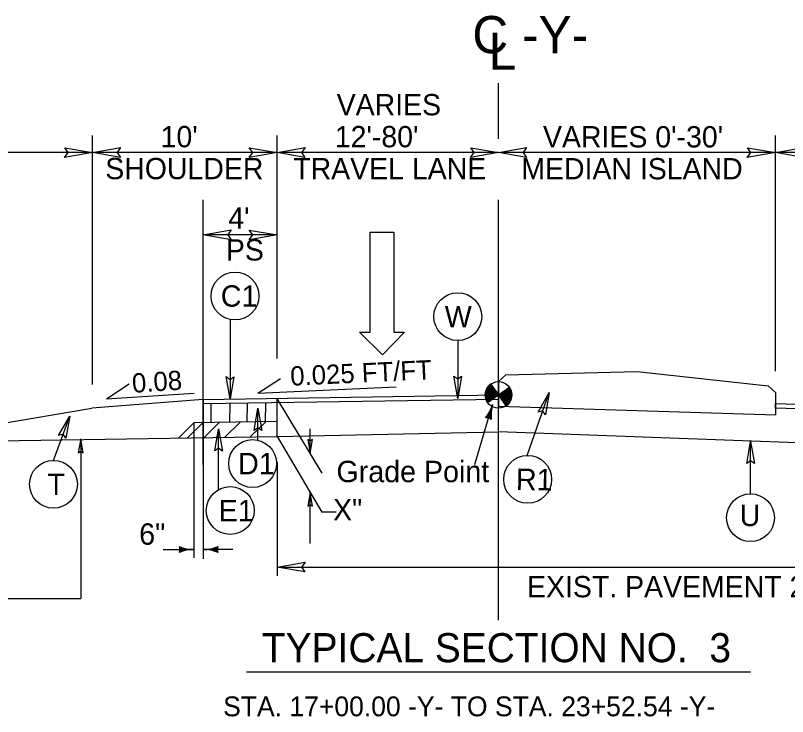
# Model space of a CAD drawing. Extents: x 2176156 to 2177167, y 76401 to 76644.
# Drawn here: x 2176967.78 to 2177009.62, y 76584.23 to 76622.21 of the extents above; entities that cross this region are included whole.
import ezdxf

# ---------------------------------------------------------------- set-up
doc = ezdxf.new("R2010")
doc.units = 0
for name, color, linetype in [('Exist Building', 7, 'Continuous'), ('Exist Building Metal Canopy', 7, 'Continuous'), ('Exist Roads Change in Surface', 7, 'Continuous'), ('Exist Roads Curbs', 7, 'Continuous'), ('Exist Roads EOP Other', 7, 'Continuous'), ('Exist Roads Soil', 7, 'Continuous'), ('Exist Structure Minor Culvert Topo', 7, 'Continuous'), ('Exist Structure Minor Drop Inlet', 7, 'Continuous'), ('Exist Utilities Other Pole CELL', 7, 'Continuous'), ('Exist Vegetation Woods Line', 7, 'Continuous'), ('Model Boundary Lines Text', 7, 'Continuous'), ('Old_Level_1', 7, 'Continuous'), ('Old_Level_3', 7, 'Continuous'), ('Prop North Arrow NAD83 for Plan Sheets CELL', 7, 'Continuous'), ('Sheet Plan CELL', 7, 'Continuous')]:
    doc.layers.add(name, color=color, linetype=linetype)

msp = doc.modelspace()

# ---------------------------------------------------------------- linework, layer by layer
at = {"layer": 'Exist Building'}
for p, q in [((2176981.96, 76599.4), (2176981.96, 76601.472)), ((2176960.844, 76599.085), (2176981.96, 76599.4))]:
    msp.add_line(p, q, dxfattribs=at)
at = {"layer": 'Exist Roads Change in Surface'}
for p, q in [((2176993.548, 76602.242), (2176993.96, 76601.65)), ((2176993.96, 76601.65), (2176994.551, 76602.062)), ((2176993.367, 76601.24), (2176993.96, 76601.65)), ((2176993.96, 76601.65), (2176993.367, 76601.24)), ((2176994.371, 76601.059), (2176993.96, 76601.65))]:
    msp.add_line(p, q, dxfattribs=at)
for points in [[(2176993.714, 76602.003), (2176993.239, 76601.672)], [(2176993.723, 76601.991), (2176993.239, 76601.654)], [(2176993.731, 76601.979), (2176993.239, 76601.637)], [(2176993.698, 76602.026), (2176993.24, 76601.708)], [(2176993.706, 76602.015), (2176993.24, 76601.69)], [(2176993.739, 76601.967), (2176993.24, 76601.62)], [(2176993.747, 76601.956), (2176993.24, 76601.602)], [(2176993.756, 76601.944), (2176993.242, 76601.586)], [(2176993.69, 76602.038), (2176993.243, 76601.727)], [(2176993.764, 76601.932), (2176993.243, 76601.57)], [(2176993.682, 76602.05), (2176993.245, 76601.746)], [(2176993.673, 76602.062), (2176993.247, 76601.766)], [(2176993.665, 76602.074), (2176993.251, 76601.786)], [(2176993.657, 76602.086), (2176993.256, 76601.807)], [(2176993.649, 76602.098), (2176993.261, 76601.828)], [(2176993.64, 76602.109), (2176993.267, 76601.85)], [(2176993.632, 76602.121), (2176993.273, 76601.871)], [(2176993.624, 76602.133), (2176993.281, 76601.894)], [(2176993.616, 76602.145), (2176993.29, 76601.918)], [(2176993.607, 76602.157), (2176993.3, 76601.943)], [(2176993.599, 76602.168), (2176993.313, 76601.969)], [(2176993.591, 76602.18), (2176993.327, 76601.996)], [(2176993.583, 76602.192), (2176993.343, 76602.026)], [(2176993.574, 76602.204), (2176993.363, 76602.057)], [(2176993.566, 76602.216), (2176993.39, 76602.093)], [(2176993.558, 76602.228), (2176993.424, 76602.134)], [(2176993.55, 76602.239), (2176993.485, 76602.195)], [(2176994.555, 76602.057), (2176994.555, 76602.057), (2176993.963, 76601.645)], [(2176994.563, 76602.045), (2176993.972, 76601.633)], [(2176994.57, 76602.032), (2176993.98, 76601.622)], [(2176994.578, 76602.021), (2176993.988, 76601.61)], [(2176994.585, 76602.008), (2176993.996, 76601.598)], [(2176994.592, 76601.995), (2176994.004, 76601.586)], [(2176994.599, 76601.982), (2176994.013, 76601.574)], [(2176994.606, 76601.97), (2176994.021, 76601.562)], [(2176994.613, 76601.957), (2176994.029, 76601.551)], [(2176994.619, 76601.943), (2176994.037, 76601.539)], [(2176994.624, 76601.929), (2176994.046, 76601.527)], [(2176993.772, 76601.92), (2176993.245, 76601.553)], [(2176993.78, 76601.908), (2176993.248, 76601.538)], [(2176993.789, 76601.896), (2176993.251, 76601.522)], [(2176993.797, 76601.884), (2176993.254, 76601.507)], [(2176993.805, 76601.873), (2176993.257, 76601.491)], [(2176993.813, 76601.861), (2176993.26, 76601.476)], [(2176993.821, 76601.849), (2176993.264, 76601.461)], [(2176993.83, 76601.837), (2176993.268, 76601.447)], [(2176993.838, 76601.825), (2176993.273, 76601.432)], [(2176993.846, 76601.813), (2176993.278, 76601.418)], [(2176993.854, 76601.802), (2176993.283, 76601.404)], [(2176993.863, 76601.79), (2176993.288, 76601.39)], [(2176993.871, 76601.778), (2176993.294, 76601.376)], [(2176993.879, 76601.766), (2176993.299, 76601.363)], [(2176993.887, 76601.754), (2176993.305, 76601.349)], [(2176993.896, 76601.743), (2176993.312, 76601.336)], [(2176993.904, 76601.731), (2176993.317, 76601.323)], [(2176993.912, 76601.719), (2176993.324, 76601.31)], [(2176993.92, 76601.707), (2176993.331, 76601.297)], [(2176993.929, 76601.695), (2176993.338, 76601.284)], [(2176993.937, 76601.683), (2176993.346, 76601.272)], [(2176993.945, 76601.671), (2176993.353, 76601.26)], [(2176993.953, 76601.66), (2176993.362, 76601.248), (2176993.362, 76601.248)], [(2176994.63, 76601.916), (2176994.054, 76601.515)], [(2176994.635, 76601.902), (2176994.062, 76601.503)], [(2176994.64, 76601.888), (2176994.07, 76601.491)], [(2176994.645, 76601.874), (2176994.079, 76601.48)], [(2176994.65, 76601.859), (2176994.087, 76601.468)], [(2176994.654, 76601.845), (2176994.095, 76601.456)], [(2176994.658, 76601.83), (2176994.103, 76601.444)], [(2176994.661, 76601.815), (2176994.112, 76601.432)], [(2176994.664, 76601.799), (2176994.12, 76601.42)], [(2176994.667, 76601.784), (2176994.128, 76601.409)], [(2176994.67, 76601.768), (2176994.136, 76601.397)], [(2176994.673, 76601.753), (2176994.145, 76601.385)], [(2176994.675, 76601.736), (2176994.153, 76601.373)], [(2176994.676, 76601.72), (2176994.161, 76601.361)], [(2176994.678, 76601.703), (2176994.169, 76601.349)], [(2176994.68, 76601.687), (2176994.177, 76601.338)], [(2176994.68, 76601.67), (2176994.186, 76601.326)], [(2176994.68, 76601.652), (2176994.194, 76601.314)], [(2176994.679, 76601.634), (2176994.202, 76601.302)], [(2176994.68, 76601.617), (2176994.21, 76601.29)], [(2176994.679, 76601.599), (2176994.219, 76601.278)], [(2176994.677, 76601.579), (2176994.227, 76601.266)], [(2176994.674, 76601.56), (2176994.235, 76601.255)], [(2176994.672, 76601.541), (2176994.243, 76601.243)], [(2176994.668, 76601.521), (2176994.252, 76601.231)], [(2176994.665, 76601.501), (2176994.26, 76601.219)], [(2176994.66, 76601.48), (2176994.268, 76601.207)], [(2176994.654, 76601.458), (2176994.276, 76601.196)], [(2176994.647, 76601.436), (2176994.285, 76601.184)], [(2176994.64, 76601.413), (2176994.293, 76601.172)], [(2176994.631, 76601.39), (2176994.301, 76601.16)], [(2176994.621, 76601.365), (2176994.309, 76601.148)], [(2176994.609, 76601.34), (2176994.317, 76601.136)], [(2176994.597, 76601.313), (2176994.326, 76601.125)], [(2176994.58, 76601.284), (2176994.334, 76601.113)], [(2176994.56, 76601.253), (2176994.342, 76601.101)], [(2176994.536, 76601.218), (2176994.35, 76601.089)], [(2176994.503, 76601.178), (2176994.359, 76601.077)], [(2176994.451, 76601.124), (2176994.367, 76601.065)]]:
    msp.add_lwpolyline(points, dxfattribs=at)
msp.add_circle((2176993.959, 76601.651), 0.721, dxfattribs=at)
for start, end in [(124.8249, 214.8249), (304.8249, 34.8249)]:
    msp.add_arc((2176993.959, 76601.651), 0.721, start, end, dxfattribs=at)
at = {"layer": 'Exist Roads Curbs'}
for points in [[(2176977.96, 76601.413), (2176993.96, 76601.65), (2176993.96, 76601.65), (2176993.96, 76601.4), (2176993.96, 76601.4), (2176977.96, 76601.163)], [(2177008.961, 76601.183), (2177008.96, 76601.183), (2177024.96, 76600.684), (2177024.96, 76600.433), (2177008.96, 76600.933), (2177008.96, 76600.933)]]:
    msp.add_lwpolyline(points, close=True, dxfattribs=at)
at = {"layer": 'Exist Roads EOP Other'}
msp.add_line((2176977.947, 76601.413), (2176971.912, 76600.93), dxfattribs=at)
at = {"layer": 'Exist Roads Soil'}
for p, q in [((2176994.354, 76602.743), (2177001.464, 76602.928)), ((2177001.464, 76602.928), (2177008.566, 76602.153)), ((2176993.96, 76602.379), (2176994.354, 76602.743)), ((2176993.96, 76602.379), (2176993.96, 76601.044)), ((2177008.961, 76601.79), (2177008.566, 76602.153)), ((2177008.961, 76601.79), (2177008.961, 76600.576)), ((2176977.96, 76601.413), (2176977.958, 76600.146)), ((2176943.96, 76596.271), (2176971.912, 76600.93)), ((2176993.96, 76601.044), (2177008.961, 76600.576)), ((2176977.454, 76600.139), (2176976.631, 76599.32)), ((2176981.96, 76600.206), (2176977.454, 76600.139))]:
    msp.add_line(p, q, dxfattribs=at)
at = {"layer": 'Exist Structure Minor Drop Inlet'}
for p, q in [((2176987.006, 76605.044), (2176987.006, 76610.476)), ((2176987.006, 76610.476), (2176988.287, 76610.476)), ((2176988.287, 76610.476), (2176988.287, 76605.044)), ((2176987.666, 76603.822), (2176986.424, 76605.044)), ((2176986.424, 76605.044), (2176987.006, 76605.044)), ((2176988.869, 76605.044), (2176987.666, 76603.822)), ((2176988.287, 76605.044), (2176988.869, 76605.044))]:
    msp.add_line(p, q, dxfattribs=at)
at = {"layer": 'Exist Utilities Other Pole CELL'}
for p, q in [((2176980.91, 76601.743), (2176982.15, 76602.539)), ((2176972.719, 76601.434), (2176973.944, 76602.253)), ((2176980.91, 76601.743), (2176988.409, 76602.093)), ((2176972.719, 76601.434), (2176977.465, 76601.747))]:
    msp.add_line(p, q, dxfattribs=at)
at = {"layer": 'Model Boundary Lines Text'}
for p, q in [((2176978.377, 76600.154), (2176978.392, 76601.171)), ((2176979.395, 76600.168), (2176979.41, 76601.182)), ((2176980.336, 76600.175), (2176980.35, 76601.201)), ((2176981.333, 76600.199), (2176981.348, 76601.211)), ((2176977.103, 76599.333), (2176977.93, 76600.143)), ((2176977.997, 76599.351), (2176978.832, 76600.17)), ((2176979.116, 76599.355), (2176979.951, 76600.174)), ((2176980.524, 76599.396), (2176981.359, 76600.215)), ((2176980.299, 76586.643), (2177007.62, 76586.643))]:
    msp.add_line(p, q, dxfattribs=at)
at = {"layer": 'Old_Level_1'}
for points in [[(2176970.45, 76615.041), (2176971.96, 76614.781), (2176970.442, 76614.513), (2176970.635, 76614.781)], [(2176973.469, 76614.521), (2176971.96, 76614.781), (2176973.478, 76615.049), (2176973.285, 76614.781)], [(2176980.45, 76615.041), (2176981.96, 76614.781), (2176980.442, 76614.513), (2176980.635, 76614.781)], [(2176983.469, 76614.521), (2176981.96, 76614.781), (2176983.478, 76615.049), (2176983.285, 76614.781)], [(2176992.45, 76615.041), (2176993.96, 76614.781), (2176992.442, 76614.513), (2176992.635, 76614.781)], [(2176995.469, 76614.521), (2176993.96, 76614.781), (2176995.478, 76615.049), (2176995.285, 76614.781)], [(2177007.45, 76615.041), (2177008.96, 76614.781), (2177007.442, 76614.513), (2177007.635, 76614.781)], [(2177010.469, 76614.521), (2177008.96, 76614.781), (2177010.478, 76615.049), (2177010.285, 76614.781)], [(2176979.469, 76610.061), (2176977.96, 76610.321), (2176979.478, 76610.589), (2176979.285, 76610.321)], [(2176980.45, 76610.581), (2176981.96, 76610.321), (2176980.442, 76610.052), (2176980.635, 76610.321)], [(2176971.444, 76598.512), (2176971.314, 76599.267), (2176971.18, 76598.508), (2176971.314, 76598.604)], [(2176983.615, 76599.237), (2176983.747, 76598.482), (2176983.879, 76599.242), (2176983.746, 76599.145)], [(2176983.88, 76595.626), (2176983.748, 76596.381), (2176983.616, 76595.621), (2176983.75, 76595.718)], [(2176983.469, 76592.069), (2176981.96, 76592.329), (2176983.478, 76592.597), (2176983.285, 76592.329)]]:
    msp.add_lwpolyline(points, close=True, dxfattribs=at)
at = {"layer": 'Old_Level_3'}
for p, q in [((2176993.96, 76615.519), (2176993.96, 76618.549)), ((2176971.96, 76602.21), (2176971.96, 76615.709)), ((2176981.96, 76603.627), (2176981.96, 76615.709)), ((2177008.96, 76602.933), (2177008.96, 76615.709)), ((2176971.96, 76614.781), (2176959.96, 76614.781)), ((2176981.96, 76614.781), (2176971.96, 76614.781)), ((2176993.96, 76614.781), (2176982.066, 76614.781)), ((2177008.96, 76614.781), (2176994.066, 76614.781)), ((2177020.96, 76614.781), (2177008.96, 76614.781)), ((2176977.96, 76597.881), (2176977.96, 76612.223)), ((2176993.96, 76589.45), (2176993.96, 76612.218)), ((2176981.96, 76610.321), (2176977.96, 76610.321)), ((2176981.959, 76601.415), (2176984.384, 76597.407)), ((2176983.747, 76598.482), (2176983.747, 76599.811)), ((2176971.314, 76599.267), (2176971.314, 76590.631)), ((2176981.96, 76599.4), (2176984.385, 76595.306)), ((2176981.96, 76598.024), (2176981.96, 76591.86)), ((2176983.748, 76593.605), (2176983.748, 76596.381)), ((2176985.165, 76595.306), (2176984.385, 76595.306)), ((2176981.96, 76592.329), (2177020.96, 76592.329)), ((2176961.746, 76590.631), (2176971.314, 76590.631))]:
    msp.add_line(p, q, dxfattribs=at)
at = {"layer": 'Prop North Arrow NAD83 for Plan Sheets CELL'}
for p, q in [((2176979.412, 76605.744), (2176979.412, 76601.441)), ((2176991.749, 76604.6), (2176991.749, 76601.467)), ((2176995.512, 76598.373), (2176996.694, 76601.779)), ((2176992.679, 76597.879), (2176993.637, 76601.133)), ((2176980.921, 76599.23), (2176980.921, 76600.929)), ((2176969.839, 76598.108), (2176970.728, 76600.511)), ((2176977.454, 76600.134), (2176977.454, 76592.819)), ((2176977.954, 76600.146), (2176977.954, 76592.778)), ((2176978.79, 76596.522), (2176978.79, 76599.818)), ((2177007.614, 76596.296), (2177007.614, 76599.138)), ((2176975.788, 76593.281), (2176977.454, 76593.281)), ((2176979.554, 76593.278), (2176977.954, 76593.278))]:
    msp.add_line(p, q, dxfattribs=at)
for points in [[(2176979.619, 76602.641), (2176979.412, 76601.441), (2176979.199, 76602.647), (2176979.412, 76602.494)], [(2176991.956, 76602.667), (2176991.749, 76601.467), (2176991.536, 76602.674), (2176991.749, 76602.52)], [(2176996.106, 76600.713), (2176996.694, 76601.779), (2176996.501, 76600.569), (2176996.349, 76600.784)], [(2176980.714, 76599.729), (2176980.921, 76600.929), (2176981.134, 76599.723), (2176980.921, 76599.876)], [(2176970.118, 76599.457), (2176970.728, 76600.511), (2176970.51, 76599.305), (2176970.363, 76599.523)], [(2176978.583, 76598.618), (2176978.79, 76599.818), (2176979.003, 76598.611), (2176978.79, 76598.764)], [(2177007.407, 76597.938), (2177007.614, 76599.138), (2177007.827, 76597.931), (2177007.614, 76598.085)]]:
    msp.add_lwpolyline(points, close=True, dxfattribs=at)
for centre in [(2176979.677, 76607.012), (2176991.749, 76605.896), (2176980.63, 76597.934), (2176995.539, 76597.078), (2176969.839, 76596.812), (2176979.419, 76595.389), (2177007.614, 76595)]:
    msp.add_circle(centre, 1.296, dxfattribs=at)
for centre, radius, start, end in [((2176991.792, 76601.649), 1.915, 320.0938, 344.3712), ((2176995.467, 76600.568), 1.915, 162.8471, 187.1245), ((2176991.792, 76601.649), 1.942, 320.7983, 334.0728), ((2176995.467, 76600.568), 1.942, 173.1456, 186.42), ((2176993.296, 76599.973), 0.448, 52.8433, 94.375), ((2176991.792, 76601.649), 1.969, 321.3787, 330.2205), ((2176991.792, 76601.649), 1.995, 321.8592, 327.3121), ((2176991.792, 76601.649), 2.022, 322.2562, 324.9003), ((2176995.467, 76600.568), 2.022, 182.318, 184.9621), ((2176995.467, 76600.568), 1.995, 179.9062, 185.3592), ((2176995.467, 76600.568), 1.969, 176.9979, 185.8397), ((2176976.246, 76593.281), 0.448, 339.2343, 20.766), ((2176977.429, 76595.196), 1.915, 246.4848, 270.7622), ((2176977.429, 76591.366), 1.915, 89.2381, 113.5155), ((2176977.429, 76595.196), 1.942, 247.1893, 260.4638), ((2176977.429, 76591.366), 1.942, 99.5365, 112.811), ((2176977.429, 76595.196), 1.969, 247.7696, 256.6115), ((2176977.429, 76591.366), 1.969, 103.3888, 112.2307), ((2176977.429, 76595.196), 1.995, 248.2502, 253.7031), ((2176977.429, 76591.366), 1.995, 106.2972, 111.7501), ((2176977.429, 76595.196), 2.022, 248.6472, 251.2913), ((2176977.429, 76591.366), 2.022, 108.709, 111.3531), ((2176977.98, 76595.193), 1.915, 269.2382, 293.5156), ((2176977.98, 76591.363), 1.915, 66.4849, 90.7623), ((2176977.98, 76595.193), 1.942, 279.5367, 292.8111), ((2176977.98, 76591.363), 1.942, 67.1895, 80.4639), ((2176977.98, 76595.193), 1.969, 283.389, 292.2308), ((2176977.98, 76591.363), 1.969, 67.7698, 76.6116), ((2176977.98, 76595.193), 1.995, 286.2973, 291.7503), ((2176977.98, 76591.363), 1.995, 68.2503, 73.7032), ((2176977.98, 76595.193), 2.022, 288.7091, 291.3532), ((2176977.98, 76591.363), 2.022, 68.6473, 71.2914), ((2176979.163, 76593.278), 0.448, 159.2344, 200.7661)]:
    msp.add_arc(centre, radius, start, end, dxfattribs=at)
at = {"layer": 'Sheet Plan CELL'}
for p in [(2176981.96, 76599.4), (2177020.947, 76598.67)]:
    msp.add_line(p, (2176993.96, 76599.648), dxfattribs=at)

# ---------------------------------------------------------------- texts
at = {"layer": 'Exist Building Metal Canopy'}
msp.add_text('TYPICAL SECTION NO.  3', height=1.5766, rotation=0, dxfattribs=at).set_placement((2176981.135, 76587.171))
at = {"layer": 'Exist Structure Minor Culvert Topo'}
for s, height, p in [('VARIES ', 1.1533, (2176985.188, 76616.8)), ("10' ", 1.1533, (2176975.647, 76615.07)), ("12'-80' ", 1.1533, (2176985.086, 76615.07)), ("VARIES 0'-30' ", 1.15334, (2176996.369, 76615.061)), ('SHOULDER', 1.1533, (2176972.646, 76613.34)), ('TRAVEL LANE', 1.15334, (2176982.834, 76613.34)), ('MEDIAN ISLAND', 1.15334, (2176995.193, 76613.331)), ("4' ", 1.1533, (2176979.312, 76610.662)), ('PS', 1.1533, (2176979.183, 76608.932)), ("EXIST. PAVEMENT 21'", 1.15334, (2176995.503, 76590.688))]:
    msp.add_text(s, height=height, dxfattribs=at).set_placement(p)
at = {"layer": 'Exist Utilities Other Pole CELL'}
for s, height, rotation, p in [('0.025 FT/FT', 1.04295, 2.6676, (2176982.696, 76602.149)), ('0.08', 1.0429, 3.7801, (2176974.129, 76601.763))]:
    msp.add_text(s, height=height, rotation=rotation, dxfattribs=at).set_placement(p)
at = {"layer": 'Exist Vegetation Woods Line'}
for s, height, p in [('C -Y- ', 2.0131, (2176992.539, 76620.168)), ('STA. 17+00.00 -Y- TO STA. 23+52.54 -Y-', 1.0742, (2176979.033, 76584.244))]:
    msp.add_text(s, height=height, dxfattribs=at).set_placement(p)
msp.add_text('L', height=2.013, rotation=359.9469, dxfattribs=at).set_placement((2176993.417, 76619.267))
at = {"layer": 'Prop North Arrow NAD83 for Plan Sheets CELL'}
for s, rotation, p in [('C1', 0.0003, (2176978.908, 76606.432)), ('W', 0.0003, (2176991.042, 76605.316)), ('D1', 0.0003, (2176979.845, 76597.354)), ('Grade Point', 0.0002, (2176985.176, 76596.925)), ('T', 0.0003, (2176969.512, 76596.232)), ('R1', 358.8249, (2176994.891, 76596.511)), ('E1', 0.0003, (2176978.791, 76594.809)), ('U', 0.0003, (2177007.027, 76594.546)), ('6"', 0.0002, (2176974.485, 76593.537))]:
    msp.add_text(s, height=1.16, rotation=rotation, dxfattribs=at).set_placement(p)
msp.add_text('X"', height=1.1533, dxfattribs=at).set_placement((2176984.995, 76594.856))

doc.saveas('drawing.dxf')
